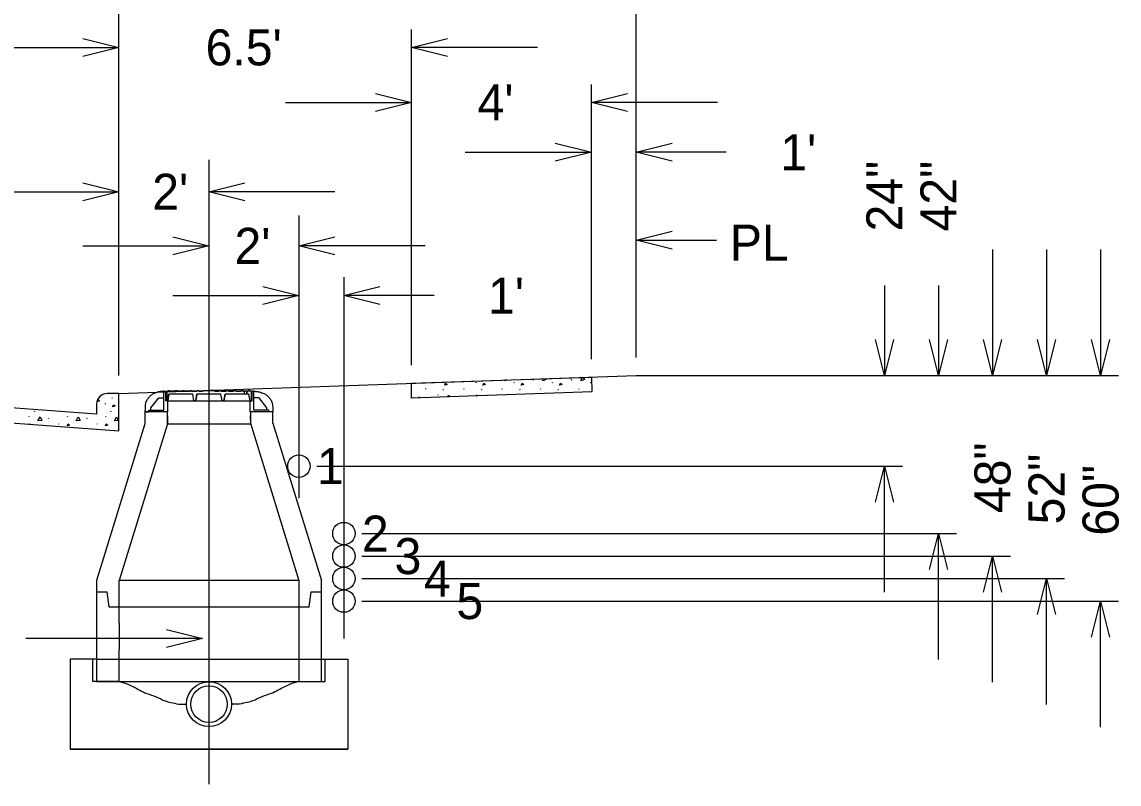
# Model space of a CAD drawing. Extents: x 524397 to 525117, y 3701341 to 3701821.
# Drawn here: x 524566.58 to 524615.33, y 3701716.61 to 3701750.49 of the extents above; entities that cross this region are included whole.
import ezdxf

# ---------------------------------------------------------------- set-up
doc = ezdxf.new("R2010")
doc.units = 0
doc.layers.add('Level 11', color=7, linetype='Continuous')

msp = doc.modelspace()

# ---------------------------------------------------------------- linework, layer by layer
at = {"layer": 'Level 11'}
for p, q in [((524593.871, 3701735.572), (524593.871, 3701755.982)), ((524570.885, 3701734.769), (524570.885, 3701753.21)), ((524593.871, 3701735.572), (524593.871, 3701753.21)), ((524570.885, 3701734.769), (524570.885, 3701750.16)), ((524583.885, 3701735.223), (524583.885, 3701750.16)), ((524565.281, 3701749.36), (524570.885, 3701749.36)), ((524569.284, 3701749.76), (524570.885, 3701749.36)), ((524569.284, 3701749.76), (524570.885, 3701749.36)), ((524570.885, 3701749.36), (524569.284, 3701748.96)), ((524570.885, 3701749.36), (524569.284, 3701748.96)), ((524583.885, 3701749.36), (524585.486, 3701749.76)), ((524589.488, 3701749.36), (524583.885, 3701749.36)), ((524585.486, 3701748.96), (524583.885, 3701749.36)), ((524583.885, 3701735.223), (524583.885, 3701747.714)), ((524591.88, 3701735.502), (524591.88, 3701747.714)), ((524578.281, 3701746.914), (524583.885, 3701746.914)), ((524582.284, 3701747.314), (524583.885, 3701746.914)), ((524583.885, 3701746.914), (524582.284, 3701746.514)), ((524591.88, 3701746.914), (524593.481, 3701747.314)), ((524597.484, 3701746.914), (524591.88, 3701746.914)), ((524593.481, 3701746.514), (524591.88, 3701746.914)), ((524591.88, 3701735.502), (524591.88, 3701745.5)), ((524593.871, 3701735.572), (524593.871, 3701745.5)), ((524590.279, 3701745.1), (524591.88, 3701744.7)), ((524593.871, 3701744.7), (524595.472, 3701745.1)), ((524586.276, 3701744.7), (524591.88, 3701744.7)), ((524591.88, 3701744.7), (524590.279, 3701744.3)), ((524597.874, 3701744.7), (524593.871, 3701744.7)), ((524595.472, 3701744.3), (524593.871, 3701744.7)), ((524574.885, 3701744.366), (524574.885, 3701716.606)), ((524570.885, 3701735.569), (524570.885, 3701743.742)), ((524574.885, 3701743.481), (524574.885, 3701742.141)), ((524569.284, 3701743.342), (524570.885, 3701742.942)), ((524574.885, 3701742.942), (524576.486, 3701743.342)), ((524565.281, 3701742.942), (524570.885, 3701742.942)), ((524570.885, 3701742.942), (524569.284, 3701742.542)), ((524580.488, 3701742.942), (524574.885, 3701742.942)), ((524576.486, 3701742.542), (524574.885, 3701742.942)), ((524578.885, 3701741.886), (524578.885, 3701741.836)), ((524578.885, 3701741.886), (524578.885, 3701729.316)), ((524593.877, 3701740.791), (524595.478, 3701741.191)), ((524573.284, 3701740.936), (524574.885, 3701740.536)), ((524578.885, 3701740.536), (524580.486, 3701740.936)), ((524593.877, 3701740.791), (524597.445, 3701740.791)), ((524595.478, 3701740.391), (524593.877, 3701740.791)), ((524569.281, 3701740.536), (524574.885, 3701740.536)), ((524574.885, 3701740.536), (524573.284, 3701740.136)), ((524584.488, 3701740.536), (524578.885, 3701740.536)), ((524580.486, 3701740.136), (524578.885, 3701740.536)), ((524609.706, 3701740.375), (524609.706, 3701734.771)), ((524612.107, 3701740.375), (524612.107, 3701734.771)), ((524614.509, 3701740.375), (524614.509, 3701734.771)), ((524574.885, 3701739.791), (524574.885, 3701739.735)), ((524578.885, 3701739.791), (524578.885, 3701739.735)), ((524580.885, 3701739.137), (524580.885, 3701723.082)), ((524580.885, 3701739.137), (524580.885, 3701739.1)), ((524577.284, 3701738.722), (524578.885, 3701738.322)), ((524580.885, 3701738.322), (524582.486, 3701738.722)), ((524604.903, 3701738.774), (524604.903, 3701734.771)), ((524607.304, 3701738.774), (524607.304, 3701734.771)), ((524573.281, 3701738.322), (524578.885, 3701738.322)), ((524578.885, 3701738.322), (524577.284, 3701737.922)), ((524580.885, 3701738.336), (524580.885, 3701737.522)), ((524584.888, 3701738.322), (524580.885, 3701738.322)), ((524582.486, 3701737.922), (524580.885, 3701738.322)), ((524578.885, 3701737.594), (524578.885, 3701737.522)), ((524604.903, 3701734.771), (524604.503, 3701736.372)), ((524605.303, 3701736.372), (524604.903, 3701734.771)), ((524607.304, 3701734.771), (524606.904, 3701736.372)), ((524607.705, 3701736.372), (524607.304, 3701734.771)), ((524609.706, 3701734.771), (524609.306, 3701736.372)), ((524610.106, 3701736.372), (524609.706, 3701734.771)), ((524612.107, 3701734.771), (524611.707, 3701736.372)), ((524612.507, 3701736.372), (524612.107, 3701734.771)), ((524614.509, 3701734.771), (524614.108, 3701736.372)), ((524614.909, 3701736.372), (524614.509, 3701734.771)), ((524570.885, 3701733.969), (524593.871, 3701734.772)), ((524583.885, 3701734.423), (524591.88, 3701734.702)), ((524591.88, 3701734.702), (524591.903, 3701734.043)), ((524593.871, 3701734.772), (524598.085, 3701734.772)), ((524593.871, 3701734.772), (524599.632, 3701734.772)), ((524593.871, 3701734.772), (524601.179, 3701734.772)), ((524593.871, 3701734.772), (524602.725, 3701734.772)), ((524593.871, 3701734.772), (524604.272, 3701734.772)), ((524603.526, 3701734.771), (524605.703, 3701734.771)), ((524603.526, 3701734.771), (524608.105, 3701734.771)), ((524603.526, 3701734.771), (524610.506, 3701734.771)), ((524603.526, 3701734.771), (524612.908, 3701734.771)), ((524603.526, 3701734.771), (524615.309, 3701734.771)), ((524583.885, 3701733.763), (524583.885, 3701734.423)), ((524585.041, 3701734.463), (524585.042, 3701734.448)), ((524586.74, 3701734.48), (524586.744, 3701734.448)), ((524588.442, 3701734.48), (524588.445, 3701734.448)), ((524589.299, 3701734.569), (524589.313, 3701734.601)), ((524590.143, 3701734.48), (524590.147, 3701734.448)), ((524591, 3701734.569), (524591.015, 3701734.601)), ((524591.845, 3701734.48), (524591.848, 3701734.448)), ((524570.885, 3701733.969), (524570.372, 3701733.969)), ((524570.372, 3701733.969), (524570.385, 3701733.969)), ((524570.591, 3701733.756), (524570.605, 3701733.788)), ((524570.885, 3701732.307), (524570.885, 3701733.969)), ((524572.303, 3701733.339), (524572.653, 3701733.777)), ((524572.653, 3701733.777), (524572.886, 3701733.776)), ((524572.886, 3701734.067), (524572.886, 3701734.067)), ((524572.886, 3701734.067), (524572.969, 3701734.067)), ((524572.886, 3701733.776), (524572.886, 3701734.067)), ((524572.886, 3701733.235), (524572.886, 3701733.776)), ((524572.969, 3701733.651), (524572.969, 3701734.067)), ((524573.011, 3701734.067), (524573.011, 3701733.651)), ((524573.053, 3701734.067), (524573.011, 3701734.067)), ((524573.011, 3701734.067), (524573.053, 3701734.067)), ((524573.011, 3701733.651), (524573.011, 3701734.067)), ((524573.052, 3701733.651), (524573.104, 3701733.943)), ((524573.104, 3701733.943), (524573.052, 3701733.651)), ((524573.053, 3701734.067), (524573.068, 3701734.109)), ((524573.053, 3701734.067), (524573.068, 3701734.109)), ((524573.068, 3701734.109), (524573.131, 3701734.109)), ((524573.068, 3701734.109), (524573.131, 3701734.109)), ((524574.167, 3701733.943), (524573.104, 3701733.943)), ((524574.167, 3701733.943), (524573.104, 3701733.943)), ((524573.146, 3701734.067), (524573.131, 3701734.109)), ((524573.131, 3701734.109), (524573.146, 3701734.067)), ((524573.377, 3701734.067), (524573.146, 3701734.067)), ((524573.146, 3701734.067), (524573.377, 3701734.067)), ((524573.377, 3701734.067), (524573.392, 3701734.109)), ((524573.377, 3701734.067), (524573.392, 3701734.109)), ((524573.392, 3701734.109), (524573.452, 3701734.109)), ((524573.392, 3701734.109), (524573.452, 3701734.109)), ((524573.467, 3701734.067), (524573.452, 3701734.109)), ((524573.452, 3701734.109), (524573.467, 3701734.067)), ((524573.693, 3701734.067), (524573.467, 3701734.067)), ((524573.467, 3701734.067), (524573.693, 3701734.067)), ((524573.693, 3701734.067), (524573.708, 3701734.109)), ((524573.693, 3701734.067), (524573.708, 3701734.109)), ((524573.708, 3701734.109), (524573.776, 3701734.109)), ((524573.708, 3701734.109), (524573.776, 3701734.109)), ((524573.791, 3701734.067), (524573.776, 3701734.109)), ((524573.776, 3701734.109), (524573.791, 3701734.067)), ((524574.02, 3701734.067), (524573.791, 3701734.067)), ((524573.791, 3701734.067), (524574.02, 3701734.067)), ((524574.02, 3701734.067), (524574.036, 3701734.109)), ((524574.02, 3701734.067), (524574.036, 3701734.109)), ((524574.036, 3701734.109), (524574.101, 3701734.109)), ((524574.036, 3701734.109), (524574.101, 3701734.109)), ((524574.116, 3701734.067), (524574.101, 3701734.109)), ((524574.101, 3701734.109), (524574.116, 3701734.067)), ((524574.343, 3701734.067), (524574.116, 3701734.067)), ((524574.116, 3701734.067), (524574.343, 3701734.067)), ((524574.218, 3701733.651), (524574.167, 3701733.943)), ((524574.218, 3701733.651), (524574.167, 3701733.943)), ((524574.302, 3701733.651), (524574.353, 3701733.943)), ((524574.353, 3701733.943), (524574.302, 3701733.651)), ((524574.343, 3701734.067), (524574.358, 3701734.109)), ((524574.343, 3701734.067), (524574.358, 3701734.109)), ((524575.416, 3701733.943), (524574.353, 3701733.943)), ((524575.416, 3701733.943), (524574.353, 3701733.943)), ((524574.358, 3701734.109), (524574.416, 3701734.109)), ((524574.358, 3701734.109), (524574.416, 3701734.109)), ((524574.432, 3701734.067), (524574.416, 3701734.109)), ((524574.416, 3701734.109), (524574.432, 3701734.067)), ((524574.618, 3701734.067), (524574.432, 3701734.067)), ((524574.432, 3701734.067), (524574.618, 3701734.067)), ((524574.618, 3701734.067), (524574.634, 3701734.109)), ((524574.618, 3701734.067), (524574.634, 3701734.109)), ((524574.634, 3701734.109), (524574.884, 3701734.109)), ((524574.634, 3701734.109), (524575.136, 3701734.109)), ((524575.136, 3701734.109), (524574.884, 3701734.109)), ((524575.151, 3701734.067), (524575.136, 3701734.109)), ((524575.136, 3701734.109), (524575.151, 3701734.067)), ((524575.338, 3701734.067), (524575.151, 3701734.067)), ((524575.151, 3701734.067), (524575.338, 3701734.067)), ((524575.338, 3701734.067), (524575.353, 3701734.109)), ((524575.338, 3701734.067), (524575.353, 3701734.109)), ((524575.411, 3701734.109), (524575.353, 3701734.109)), ((524575.353, 3701734.109), (524575.411, 3701734.109)), ((524575.426, 3701734.067), (524575.411, 3701734.109)), ((524575.411, 3701734.109), (524575.426, 3701734.067)), ((524575.468, 3701733.651), (524575.416, 3701733.943)), ((524575.468, 3701733.651), (524575.416, 3701733.943)), ((524575.653, 3701734.067), (524575.426, 3701734.067)), ((524575.426, 3701734.067), (524575.653, 3701734.067)), ((524575.551, 3701733.651), (524575.602, 3701733.943)), ((524575.602, 3701733.943), (524575.551, 3701733.651)), ((524576.665, 3701733.943), (524575.602, 3701733.943)), ((524576.446, 3701733.943), (524575.602, 3701733.943)), ((524575.653, 3701734.067), (524575.669, 3701734.109)), ((524575.653, 3701734.067), (524575.669, 3701734.109)), ((524575.734, 3701734.109), (524575.669, 3701734.109)), ((524575.669, 3701734.109), (524575.734, 3701734.109)), ((524575.749, 3701734.067), (524575.734, 3701734.109)), ((524575.734, 3701734.109), (524575.749, 3701734.067)), ((524575.978, 3701734.067), (524575.749, 3701734.067)), ((524575.749, 3701734.067), (524575.978, 3701734.067)), ((524575.978, 3701734.067), (524575.993, 3701734.109)), ((524575.978, 3701734.067), (524575.993, 3701734.109)), ((524576.061, 3701734.109), (524575.993, 3701734.109)), ((524575.993, 3701734.109), (524576.061, 3701734.109)), ((524576.076, 3701734.067), (524576.061, 3701734.109)), ((524576.061, 3701734.109), (524576.076, 3701734.067)), ((524576.303, 3701734.067), (524576.076, 3701734.067)), ((524576.076, 3701734.067), (524576.303, 3701734.067)), ((524576.303, 3701734.067), (524576.317, 3701734.109)), ((524576.303, 3701734.067), (524576.317, 3701734.109)), ((524576.377, 3701734.109), (524576.317, 3701734.109)), ((524576.317, 3701734.109), (524576.377, 3701734.109)), ((524576.392, 3701734.067), (524576.377, 3701734.109)), ((524576.377, 3701734.109), (524576.392, 3701734.067)), ((524576.623, 3701734.067), (524576.392, 3701734.067)), ((524576.392, 3701734.067), (524576.446, 3701734.067)), ((524576.446, 3701734.067), (524576.446, 3701733.943)), ((524576.446, 3701734.067), (524576.446, 3701733.943)), ((524576.571, 3701734.067), (524576.571, 3701733.943)), ((524576.571, 3701734.067), (524576.623, 3701734.067)), ((524576.571, 3701733.943), (524576.571, 3701734.067)), ((524576.665, 3701733.943), (524576.571, 3701733.943)), ((524576.623, 3701734.067), (524576.639, 3701734.109)), ((524576.623, 3701734.067), (524576.639, 3701734.109)), ((524576.701, 3701734.109), (524576.639, 3701734.109)), ((524576.639, 3701734.109), (524576.701, 3701734.109)), ((524576.717, 3701733.651), (524576.665, 3701733.943)), ((524576.717, 3701733.651), (524576.665, 3701733.943)), ((524576.716, 3701734.067), (524576.701, 3701734.109)), ((524576.701, 3701734.109), (524576.716, 3701734.067)), ((524576.758, 3701734.067), (524576.716, 3701734.067)), ((524576.716, 3701734.067), (524576.758, 3701734.067)), ((524576.758, 3701734.067), (524576.758, 3701733.651)), ((524576.758, 3701734.067), (524576.758, 3701733.651)), ((524576.8, 3701733.651), (524576.8, 3701734.067)), ((524576.883, 3701734.067), (524576.8, 3701734.067)), ((524576.883, 3701733.776), (524576.883, 3701734.067)), ((524577.116, 3701733.777), (524576.883, 3701733.776)), ((524576.883, 3701733.235), (524576.883, 3701733.776)), ((524577.466, 3701733.339), (524577.116, 3701733.777)), ((524591.903, 3701734.043), (524583.885, 3701733.763)), ((524584.23, 3701733.812), (524584.244, 3701733.844)), ((524584.518, 3701734.157), (524584.532, 3701734.189)), ((524585.072, 3701733.894), (524585.086, 3701733.926)), ((524585.281, 3701734.157), (524585.295, 3701734.136)), ((524585.295, 3701734.149), (524585.31, 3701734.128)), ((524585.941, 3701733.835), (524585.946, 3701733.844)), ((524586.219, 3701734.157), (524586.233, 3701734.189)), ((524586.773, 3701733.894), (524586.787, 3701733.926)), ((524586.983, 3701734.157), (524586.997, 3701734.136)), ((524586.997, 3701734.149), (524587.011, 3701734.128)), ((524587.921, 3701734.157), (524587.935, 3701734.189)), ((524588.488, 3701733.924), (524588.489, 3701733.926)), ((524588.684, 3701734.157), (524588.698, 3701734.136)), ((524588.698, 3701734.149), (524588.713, 3701734.128)), ((524589.622, 3701734.157), (524589.636, 3701734.189)), ((524590.386, 3701734.157), (524590.4, 3701734.136)), ((524590.4, 3701734.149), (524590.414, 3701734.128)), ((524591.324, 3701734.157), (524591.338, 3701734.189)), ((524569.885, 3701733.045), (524565.885, 3701733.347)), ((524569.885, 3701733.507), (524569.885, 3701733.045)), ((524570.274, 3701733.521), (524570.277, 3701733.489)), ((524572.219, 3701733.151), (524572.219, 3701733.235)), ((524572.219, 3701733.235), (524572.303, 3701733.235)), ((524572.303, 3701733.235), (524572.303, 3701733.339)), ((524572.303, 3701733.235), (524572.886, 3701733.235)), ((524573.052, 3701733.651), (524572.969, 3701733.651)), ((524573.011, 3701733.651), (524576.758, 3701733.651)), ((524573.052, 3701733.651), (524573.011, 3701733.651)), ((524573.052, 3701733.151), (524573.052, 3701733.651)), ((524574.302, 3701733.651), (524574.218, 3701733.651)), ((524575.551, 3701733.651), (524575.468, 3701733.651)), ((524576.717, 3701733.151), (524576.717, 3701733.651)), ((524576.717, 3701733.651), (524576.8, 3701733.651)), ((524576.758, 3701733.651), (524576.717, 3701733.651)), ((524577.466, 3701733.235), (524576.883, 3701733.235)), ((524577.466, 3701733.235), (524577.466, 3701733.339)), ((524577.549, 3701733.235), (524577.466, 3701733.235)), ((524577.549, 3701733.151), (524577.549, 3701733.235)), ((524566.904, 3701732.935), (524566.918, 3701732.967)), ((524567.113, 3701733.198), (524567.127, 3701733.177)), ((524567.127, 3701733.19), (524567.142, 3701733.169)), ((524567.763, 3701732.853), (524567.778, 3701732.885)), ((524568.605, 3701732.935), (524568.619, 3701732.967)), ((524569.465, 3701732.853), (524569.479, 3701732.885)), ((524570.307, 3701732.935), (524570.321, 3701732.967)), ((524570.516, 3701733.198), (524570.53, 3701733.177)), ((524570.53, 3701733.19), (524570.545, 3701733.169)), ((524572.042, 3701733.151), (524572.042, 3701732.618)), ((524573.052, 3701733.151), (524572.042, 3701733.151)), ((524572.042, 3701733.151), (524572.219, 3701733.151)), ((524573.042, 3701732.619), (524573.042, 3701733.151)), ((524573.042, 3701732.985), (524573.042, 3701732.659)), ((524577.727, 3701733.151), (524576.717, 3701733.151)), ((524576.727, 3701733.151), (524576.727, 3701732.652)), ((524576.727, 3701732.818), (524576.727, 3701732.991)), ((524577.727, 3701733.151), (524576.728, 3701733.151)), ((524577.727, 3701733.151), (524577.549, 3701733.151)), ((524577.727, 3701732.652), (524577.727, 3701733.151)), ((524565.885, 3701732.685), (524570.885, 3701732.307)), ((524568.207, 3701732.626), (524568.222, 3701732.604)), ((524572.042, 3701732.618), (524569.892, 3701725.651)), ((524569.909, 3701732.626), (524569.923, 3701732.604)), ((524573.042, 3701732.619), (524570.891, 3701725.651)), ((524573.042, 3701732.619), (524576.727, 3701732.619)), ((524576.727, 3701732.652), (524578.887, 3701725.656)), ((524577.727, 3701732.652), (524579.886, 3701725.656)), ((524579.685, 3701730.742), (524605.703, 3701730.742)), ((524604.503, 3701729.141), (524604.903, 3701730.742)), ((524604.903, 3701725.138), (524604.903, 3701730.742)), ((524604.903, 3701730.742), (524605.303, 3701729.141)), ((524581.685, 3701727.742), (524608.105, 3701727.742)), ((524606.904, 3701726.141), (524607.304, 3701727.742)), ((524607.304, 3701722.138), (524607.304, 3701727.742)), ((524607.304, 3701727.742), (524607.705, 3701726.141)), ((524581.685, 3701726.742), (524610.506, 3701726.742)), ((524609.306, 3701725.141), (524609.706, 3701726.742)), ((524609.706, 3701721.138), (524609.706, 3701726.742)), ((524609.706, 3701726.742), (524610.106, 3701725.141)), ((524569.892, 3701725.651), (524569.892, 3701724.49)), ((524578.887, 3701725.655), (524570.891, 3701725.651)), ((524570.891, 3701724.49), (524570.891, 3701725.651)), ((524578.887, 3701725.656), (524578.887, 3701724.49)), ((524578.887, 3701725.656), (524578.887, 3701725.156)), ((524579.886, 3701725.156), (524579.886, 3701725.656)), ((524579.886, 3701725.156), (524579.886, 3701725.656)), ((524581.685, 3701725.742), (524612.908, 3701725.742)), ((524611.707, 3701724.141), (524612.107, 3701725.742)), ((524612.107, 3701720.138), (524612.107, 3701725.742)), ((524612.107, 3701725.742), (524612.507, 3701724.141)), ((524569.892, 3701725.358), (524569.892, 3701725.156)), ((524569.892, 3701725.156), (524570.35, 3701725.156)), ((524569.892, 3701725.156), (524570.35, 3701725.156)), ((524569.892, 3701725.156), (524569.892, 3701723.769)), ((524570.35, 3701725.156), (524570.433, 3701724.49)), ((524570.35, 3701725.156), (524570.433, 3701724.49)), ((524570.891, 3701725.156), (524570.891, 3701725.358)), ((524570.891, 3701723.769), (524570.891, 3701725.156)), ((524578.887, 3701725.358), (524578.887, 3701725.156)), ((524578.887, 3701725.358), (524578.887, 3701725.156)), ((524578.887, 3701725.156), (524578.887, 3701721.159)), ((524578.887, 3701725.156), (524578.887, 3701721.159)), ((524579.345, 3701724.49), (524579.428, 3701725.156)), ((524579.345, 3701724.49), (524579.428, 3701725.156)), ((524579.428, 3701725.156), (524579.886, 3701725.156)), ((524579.428, 3701725.156), (524579.886, 3701725.156)), ((524579.428, 3701725.156), (524579.886, 3701725.156)), ((524579.886, 3701721.159), (524579.886, 3701725.358)), ((524579.886, 3701724.49), (524579.886, 3701725.156)), ((524569.892, 3701724.768), (524569.892, 3701721.159)), ((524570.433, 3701724.49), (524570.891, 3701724.49)), ((524570.433, 3701724.49), (524570.891, 3701724.49)), ((524570.891, 3701724.49), (524578.887, 3701724.49)), ((524570.891, 3701724.49), (524578.887, 3701724.49)), ((524578.887, 3701724.49), (524579.345, 3701724.49)), ((524578.887, 3701724.49), (524579.345, 3701724.49)), ((524581.685, 3701724.742), (524615.309, 3701724.742)), ((524614.108, 3701723.141), (524614.509, 3701724.742)), ((524614.509, 3701719.138), (524614.509, 3701724.742)), ((524614.509, 3701724.742), (524614.909, 3701723.141)), ((524570.891, 3701723.769), (524570.891, 3701722.585)), ((524572.995, 3701723.484), (524574.596, 3701723.084)), ((524574.596, 3701723.084), (524566.753, 3701723.084)), ((524574.596, 3701723.084), (524572.995, 3701722.684)), ((524570.891, 3701721.159), (524570.891, 3701722.585)), ((524569.892, 3701722.158), (524568.726, 3701722.158)), ((524568.726, 3701722.158), (524568.726, 3701718.161)), ((524569.726, 3701721.159), (524569.726, 3701722.158)), ((524569.892, 3701722.158), (524579.886, 3701722.158)), ((524579.886, 3701722.158), (524581.052, 3701722.158)), ((524580.053, 3701721.159), (524580.053, 3701722.158)), ((524581.052, 3701722.158), (524581.052, 3701718.161)), ((524569.892, 3701721.159), (524569.726, 3701721.159)), ((524569.892, 3701721.159), (524569.726, 3701721.159)), ((524569.892, 3701721.159), (524570.891, 3701721.159)), ((524570.891, 3701721.159), (524569.892, 3701721.159)), ((524570.891, 3701721.159), (524569.892, 3701721.159)), ((524570.891, 3701721.159), (524578.887, 3701721.159)), ((524578.887, 3701721.159), (524579.886, 3701721.159)), ((524578.887, 3701721.159), (524579.886, 3701721.159)), ((524579.886, 3701721.159), (524580.053, 3701721.159)), ((524581.052, 3701718.161), (524568.726, 3701718.161)), ((524568.726, 3701718.161), (524581.052, 3701718.161))]:
    msp.add_line(p, q, dxfattribs=at)
for points in [[(524585.363, 3701734.342), (524585.406, 3701734.431), (524585.477, 3701734.377), (524585.363, 3701734.342)], [(524587.065, 3701734.342), (524587.107, 3701734.431), (524587.178, 3701734.377), (524587.065, 3701734.342)], [(524588.029, 3701734.533), (524588.034, 3701734.568)], [(524588.112, 3701734.571), (524588.033, 3701734.534)], [(524588.766, 3701734.342), (524588.809, 3701734.431), (524588.88, 3701734.377), (524588.766, 3701734.342)], [(524589.731, 3701734.533), (524589.744, 3701734.628)], [(524589.86, 3701734.632), (524589.886, 3701734.604), (524589.734, 3701734.534)], [(524590.468, 3701734.342), (524590.51, 3701734.431), (524590.581, 3701734.377), (524590.468, 3701734.342)], [(524591.432, 3701734.533), (524591.454, 3701734.687)], [(524591.506, 3701734.689), (524591.588, 3701734.604), (524591.436, 3701734.534)], [(524583.885, 3701733.811), (524583.906, 3701733.764)], [(524585.506, 3701733.82), (524585.548, 3701733.897), (524585.581, 3701733.822)], [(524587.24, 3701733.88), (524587.249, 3701733.897), (524587.257, 3701733.881)], [(524569.949, 3701733.715), (524570.017, 3701733.645), (524569.912, 3701733.597)], [(524570.598, 3701733.383), (524570.641, 3701733.472), (524570.712, 3701733.418), (524570.598, 3701733.383)], [(524567.284, 3701732.757), (524567.38, 3701732.938), (524567.454, 3701732.771), (524567.287, 3701732.757)], [(524568.985, 3701732.757), (524569.081, 3701732.938), (524569.156, 3701732.771), (524568.989, 3701732.757)], [(524570.687, 3701732.757), (524570.783, 3701732.938), (524570.857, 3701732.771), (524570.69, 3701732.757)], [(524566.914, 3701732.607), (524566.921, 3701732.622), (524566.945, 3701732.605)], [(524568.58, 3701732.533), (524568.623, 3701732.622), (524568.694, 3701732.569), (524568.58, 3701732.533)], [(524570.282, 3701732.533), (524570.324, 3701732.622), (524570.395, 3701732.569), (524570.282, 3701732.533)]]:
    msp.add_lwpolyline(points, dxfattribs=at)
for centre, radius in [((524578.885, 3701730.742), 0.5), ((524580.885, 3701727.742), 0.5), ((524580.885, 3701726.742), 0.5), ((524580.885, 3701725.742), 0.5), ((524580.885, 3701724.742), 0.5), ((524574.889, 3701720.159), 0.999), ((524574.889, 3701720.159), 0.814)]:
    msp.add_circle(centre, radius, dxfattribs=at)
msp.add_arc((524570.378, 3701733.475), 0.494, 89.2332, 176.2921, dxfattribs=at)
for points in [[(524572.886, 3701734.067), (524572.813, 3701734.066), (524572.734, 3701734.056), (524572.665, 3701734.044), (524572.606, 3701734.032), (524572.542, 3701734.004), (524572.484, 3701733.991), (524572.341, 3701733.911), (524572.237, 3701733.825), (524572.146, 3701733.707), (524572.07, 3701733.543), (524572.049, 3701733.311), (524572.042, 3701733.151)], [(524576.883, 3701734.067), (524576.956, 3701734.066), (524577.035, 3701734.056), (524577.104, 3701734.044), (524577.163, 3701734.032), (524577.227, 3701734.004), (524577.286, 3701733.991), (524577.429, 3701733.911), (524577.532, 3701733.825), (524577.623, 3701733.707), (524577.699, 3701733.543), (524577.72, 3701733.311), (524577.727, 3701733.151)], [(524570.891, 3701721.159), (524571.306, 3701721.034), (524571.809, 3701720.783), (524572.124, 3701720.636), (524572.544, 3701720.489), (524572.943, 3701720.3), (524573.279, 3701720.217), (524573.615, 3701720.154), (524573.89, 3701720.159)], [(524578.887, 3701721.159), (524578.473, 3701721.034), (524577.969, 3701720.783), (524577.654, 3701720.636), (524577.234, 3701720.489), (524576.835, 3701720.3), (524576.499, 3701720.217), (524576.163, 3701720.154), (524575.888, 3701720.159)]]:
    msp.add_spline(points, degree=3, dxfattribs=at)

# ---------------------------------------------------------------- texts
for s, p in [("6.5'", (524574.738, 3701748.559)), ("4'", (524586.823, 3701746.113)), ("1'", (524600.275, 3701743.899)), ("2'", (524572.365, 3701742.141)), ("2'", (524576.02, 3701739.735)), ('PL', (524598.034, 3701739.879)), ("1'", (524587.289, 3701737.522)), ('1', (524579.685, 3701729.941)), ('2', (524581.685, 3701726.941)), ('3', (524583.135, 3701725.941)), ('4', (524584.434, 3701724.941)), ('5', (524585.884, 3701723.941))]:
    msp.add_text(s, height=1.601, dxfattribs=at).set_placement(p)
for s, p in [('24"', (524605.703, 3701741.175)), ('42"', (524608.105, 3701741.175)), ('48"', (524610.506, 3701728.651)), ('52"', (524612.908, 3701728.151)), ('60"', (524615.309, 3701727.651))]:
    msp.add_text(s, height=1.601, rotation=90, dxfattribs=at).set_placement(p)

doc.saveas('drawing.dxf')
